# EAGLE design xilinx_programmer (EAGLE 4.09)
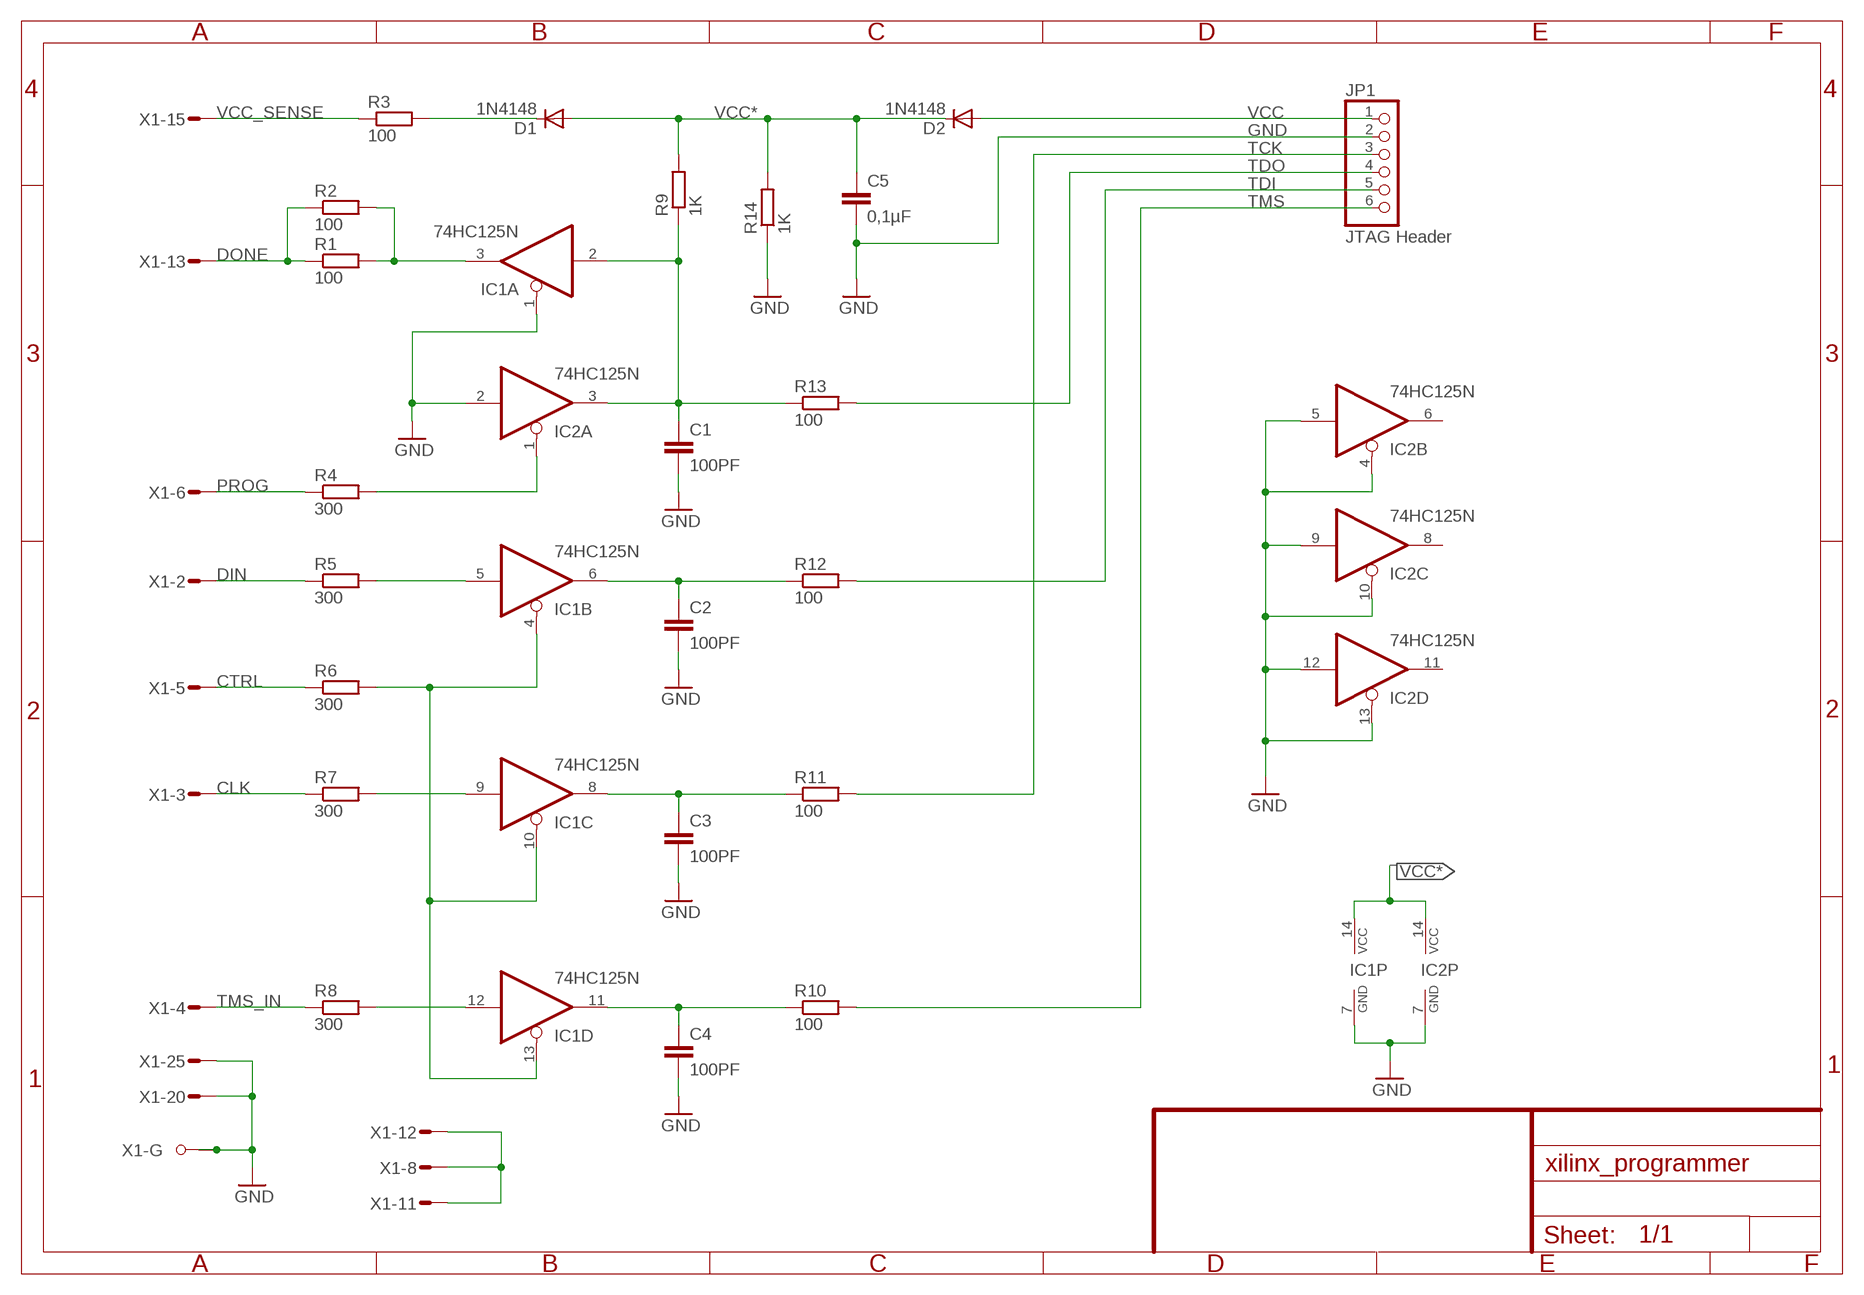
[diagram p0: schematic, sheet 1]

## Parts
C1  100PF  C-EU050-025X075  [C050-025X075]
C2  100PF  C-EU050-025X075  [C050-025X075]
C3  100PF  C-EU050-025X075  [C050-025X075]
C4  100PF  C-EU050-025X075  [C050-025X075]
C5  0,1µF  C-EU050-025X075  [C050-025X075]
D1  1N4148  [DO35-10]
D2  1N4148  [DO35-10]
IC1  74HC125N  [DIL14]
IC2  74HC125N  [DIL14]
JP1  JTAG Header  PINHD-1X6  [1X06]
R1  100  R-EU_0207/10  [0207/10]
R2  100  R-EU_0207/10  [0207/10]
R3  100  R-EU_0207/10  [0207/10]
R4  300  R-EU_0207/10  [0207/10]
R5  300  R-EU_0207/10  [0207/10]
R6  300  R-EU_0207/10  [0207/10]
R7  300  R-EU_0207/10  [0207/10]
R8  300  R-EU_0207/10  [0207/10]
R9  1K  R-EU_0207/10  [0207/10]
R10  100  R-EU_0207/10  [0207/10]
R11  100  R-EU_0207/10  [0207/10]
R12  100  R-EU_0207/10  [0207/10]
R13  100  R-EU_0207/10  [0207/10]
R14  1K  R-EU_0207/10  [0207/10]
X1  M25HPS  [M25HP]

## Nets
CLK: R7.1 X1.3(-3:M)
CTRL: R6.1 X1.5(-5:M)
DIN: R5.1 X1.2(-2:M)
DONE: R1.1 R2.1 X1.13(-13:M)
GND: C1.2 C2.2 C3.2 C4.2 C5.2 IC1.1(A:OE) IC1.7(P:GND) IC2.2(A:I) IC2.4(B:OE) IC2.5(B:I) IC2.7(P:GND) IC2.9(C:I) IC2.10(C:OE) IC2.12(D:I) IC2.13(D:OE) JP1.2 R14.1 X1.20(-20:M) X1.25(-25:M) X1.G1(-G:G1) X1.G2(-G:G2)
N$1: D1.C R3.2
N$3: X1.8(-8:M) X1.11(-11:M) X1.12(-12:M)
N$5: IC1.3(A:O) R1.2 R2.2
N$7: C2.1 IC1.6(B:O) R12.1
N$8: C1.1 IC1.2(A:I) IC2.3(A:O) R9.1 R13.1
N$9: IC2.1(A:OE) R4.2
N$10: IC1.5(B:I) R5.2
N$11: IC1.4(B:OE) IC1.10(C:OE) IC1.13(D:OE) R6.2
N$12: IC1.9(C:I) R7.2
N$13: IC1.12(D:I) R8.2
N$14: C3.1 IC1.8(C:O) R11.1
N$15: C4.1 IC1.11(D:O) R10.1
PROG: R4.1 X1.6(-6:M)
TCK: JP1.3 R11.2
TDI: JP1.5 R12.2
TDO: JP1.4 R13.2
TMS: JP1.6 R10.2
TMS_IN: R8.1 X1.4(-4:M)
VCC: D2.A JP1.1
VCC*: C5.1 D1.A D2.C IC1.14(P:VCC) IC2.14(P:VCC) R9.2 R14.2
VCC_SENSE: R3.1 X1.15(-15:M)
Unconnected: IC2.6(B:O) IC2.8(C:O) IC2.11(D:O) X1.1(-1:M) X1.7(-7:M) X1.9(-9:M) X1.10(-10:M) X1.14(-14:M) X1.16(-16:M) X1.17(-17:M) X1.18(-18:M) X1.19(-19:M) X1.21(-21:M) X1.22(-22:M) X1.23(-23:M) X1.24(-24:M)

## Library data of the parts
C1-C5 = rcl:C-EU: CAPACITOR, European symbol
D1 D2 = diode:1N4148: DIODE
IC1 IC2 = 74xx-eu:74*125: Quad bus BUFFER, 3-state
JP1 = pinhead:PINHD-1X6: PIN HEADER
R1-R14 = rcl:R-EU_: RESISTOR, European symbol
X1 = con-subd:M25HPS: SUB-D

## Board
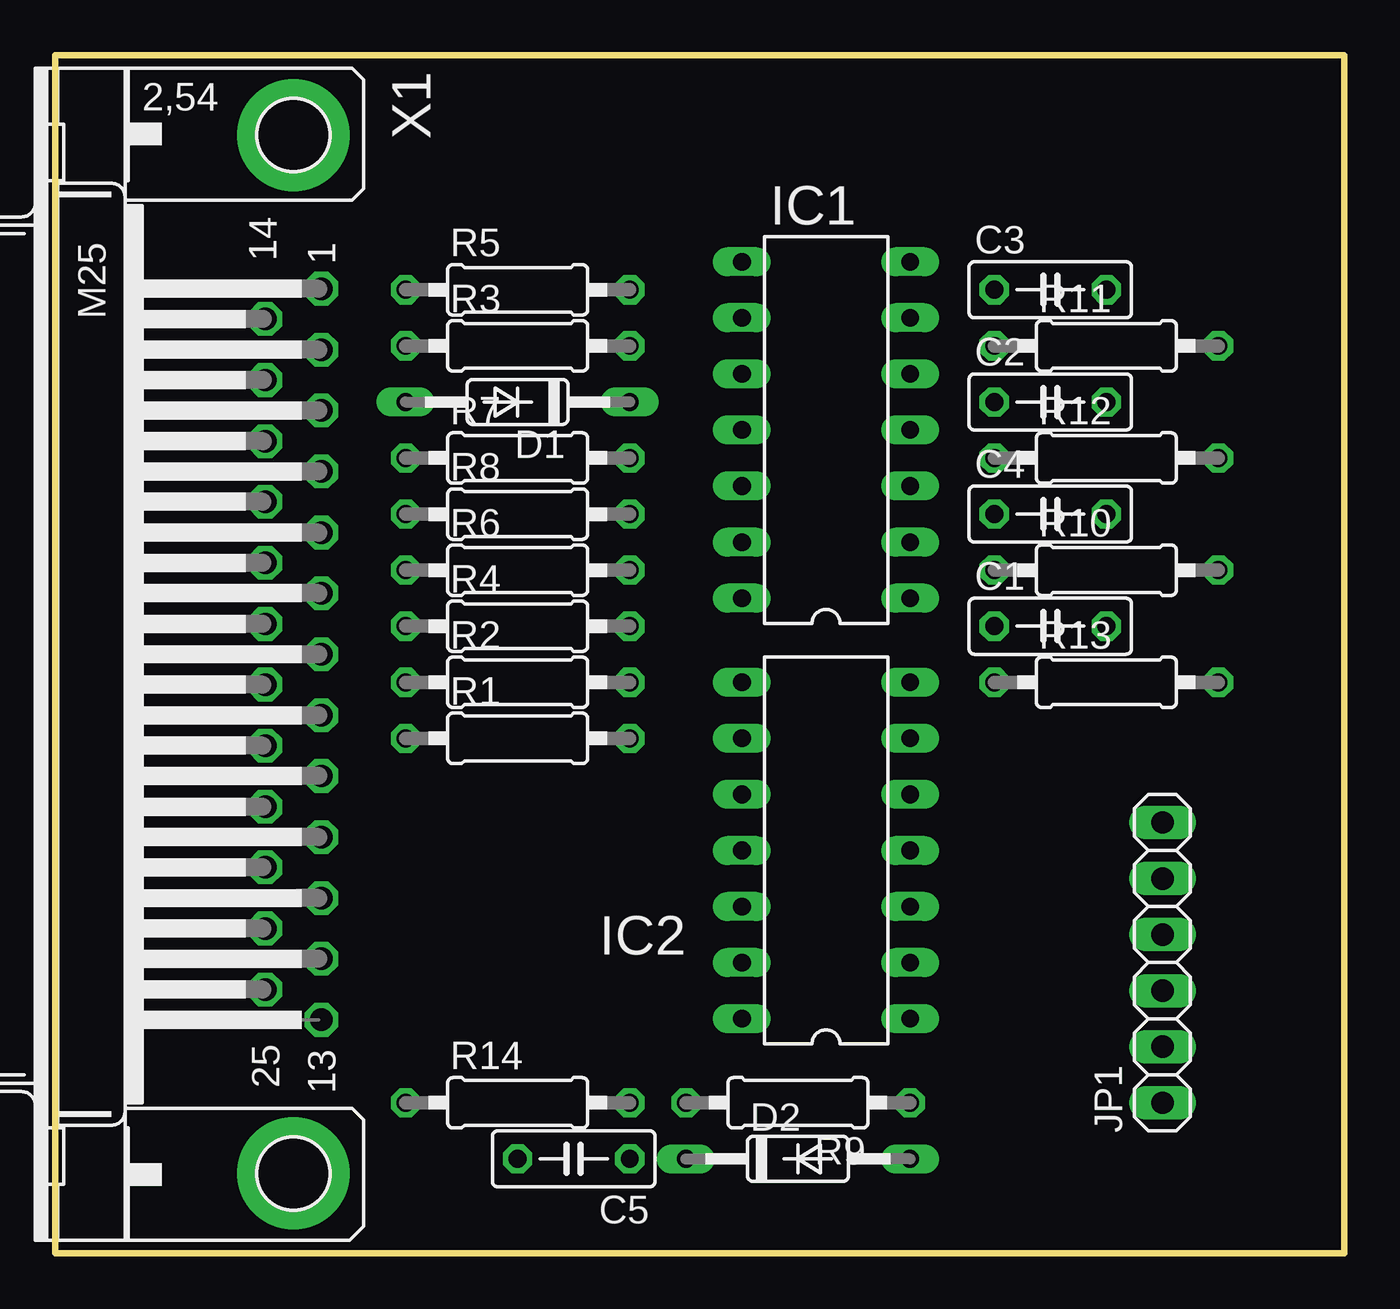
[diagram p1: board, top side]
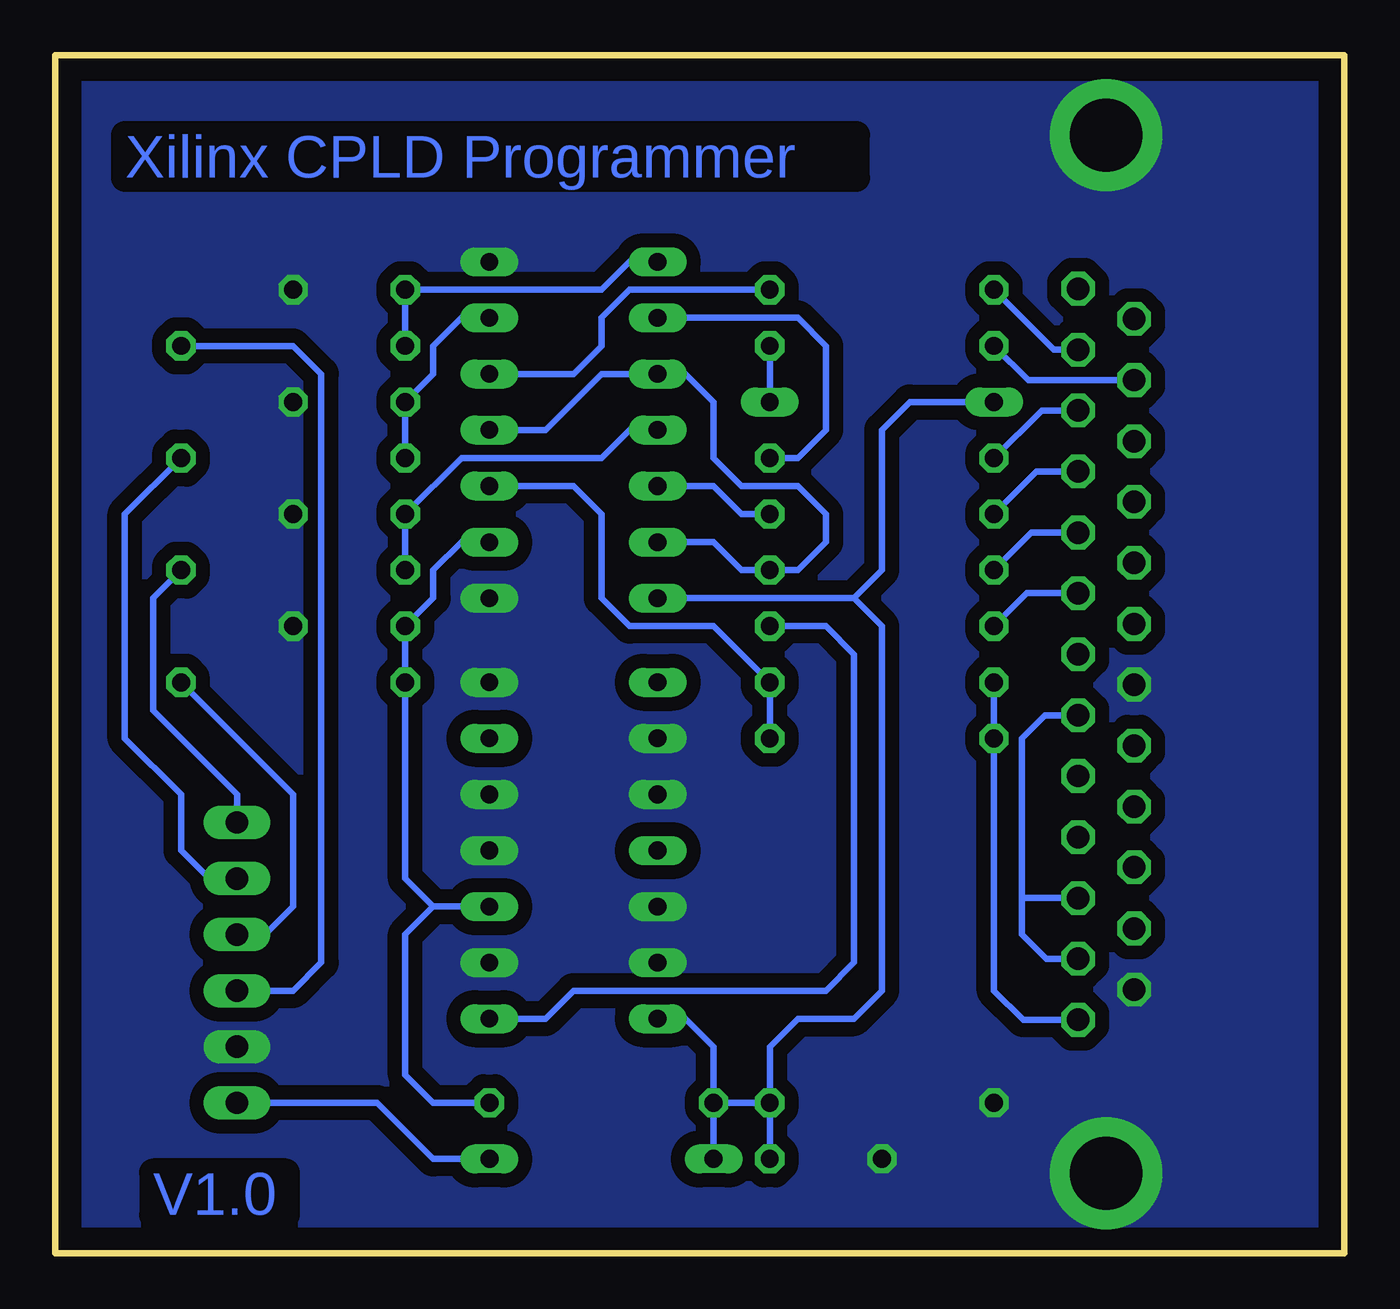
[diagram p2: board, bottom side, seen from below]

Size 58.4 x 54.28 mm. Coordinates in mm from the lower left corner, seen from the top.
Outline: 0,0 58.4,0 58.4,54.28 0,54.28 0,0
Copper layers 16: Bottom 0.035mm
Design rules "default": minimum track width 10mil, minimum drill 24mil, track to track 8mil, track to pad 8mil, pad to pad 8mil, via to via 8mil, smd to smd 8mil, copper to edge 40mil, drill to drill 8mil, minimum pad ring 10mil, minimum via ring 8mil, stop-mask expansion 4mil, vias tented up to drill 0mil, thermal gap 10mil

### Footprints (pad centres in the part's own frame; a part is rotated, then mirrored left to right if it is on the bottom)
C050-025X075 = drill 0.813 octagon: 1 -2.54,0; 2 2.54,0
DO35-10 = drill 0.813 long: A 5.08,0; C -5.08,0
DIL14 = drill 0.8 long: 1 -7.62,-3.81; 2 -5.08,-3.81; 3 -2.54,-3.81; 4 0,-3.81; 5 2.54,-3.81; 6 5.08,-3.81; 7 7.62,-3.81; 8 7.62,3.81; 9 5.08,3.81; 10 2.54,3.81; 11 0,3.81; 12 -2.54,3.81; 13 -5.08,3.81; 14 -7.62,3.81
1X06 = drill 1.016 long: 1 -6.35,0; 2 -3.81,0; 3 -1.27,0; 4 1.27,0; 5 3.81,0; 6 6.35,0
0207/10 = drill 0.813 octagon: 1 -5.08,0; 2 5.08,0
M25HP = drill 1.016 octagon: 1 -16.561,1.27; 2 -13.792,1.27; 3 -11.049,1.27; 4 -8.28,1.27; 5 -5.512,1.27; 6 -2.769,1.27; 7 0,1.27; 8 2.769,1.27; 9 5.512,1.27; 10 8.28,1.27; 11 11.049,1.27; 12 13.792,1.27; 13 16.561,1.27; 14 -15.189,-1.27; 15 -12.421,-1.27; 16 -9.652,-1.27; 17 -6.909,-1.27; 18 -4.14,-1.27; 19 -1.372,-1.27; 20 1.372,-1.27; 21 4.14,-1.27; 22 6.909,-1.27; 23 9.652,-1.27; 24 12.421,-1.27; 25 15.189,-1.27 | drill 3.302 pad 5.08 round: G1 -23.52,0; G2 23.52,0

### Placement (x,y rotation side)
C1  45.08,28.41 0 top
C2  45.08,38.57 0 top
C3  45.08,43.65 0 top
C4  45.08,33.49 0 top
C5  23.49,4.28 180 top
D1  20.95,38.57 180 top
D2  33.65,4.28 0 top
IC1  34.92,37.3 90 top
IC2  34.92,18.25 90 top
JP1  50.16,13.17 90 top
R1  20.95,23.33 0 top
R2  20.95,25.87 0 top
R3  20.95,41.11 0 top
R4  20.95,28.41 0 top
R5  20.95,43.65 0 top
R6  20.95,30.95 0 top
R7  20.95,36.03 0 top
R8  20.95,33.49 0 top
R9  33.65,6.82 180 top
R10  47.62,30.95 0 top
R11  47.62,41.11 0 top
R12  47.62,36.03 0 top
R13  47.62,25.87 0 top
R14  20.95,6.82 0 top
X1  10.79,27.14 270 top

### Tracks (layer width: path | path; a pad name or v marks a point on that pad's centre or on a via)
CLK
  Bottom 0.305: X1.3 13.71,38.19 R7.1
CTRL
  Bottom 0.305: X1.5 14.17,32.65 R6.1
DIN
  Bottom 0.305: X1.2 13.15,40.93 R5.1
DONE
  Bottom 0.305: R2.1 R1.1 15.87,11.9 14.55,10.58 X1.13
GND
  pour Bottom (isolate 0.635, no thermals): 0.63,53.81 57.78,53.81 57.78,0.47 0.63,0.47
N$1
  Bottom 0.305: D1.C R3.2
N$3
  Bottom 0.305: X1.8 13.56,24.37 14.6,23.33 14.6,16.09 | X1.12 13.51,13.35 14.6,14.44 14.6,16.09 | 14.6,16.09 X1.11
N$5
  Bottom 0.305: R1.2 R2.2 28.57,28.41 32.38,28.41 33.65,29.68 33.65,33.49 34.92,34.76 IC1.3
N$7
  Bottom 0.305: R12.1 C2.1 41.27,39.84 41.27,41.11 40,42.38 IC1.6
N$8
  Bottom 0.305: R9.1 41.27,6.82 42.54,8.09 42.54,14.44 41.27,15.71 | 41.27,15.71 IC2.3 | 41.27,15.71 42.54,16.98 R13.1 C1.1 41.27,29.68 41.27,30.95 40,32.22 IC1.2
N$9
  Bottom 0.305: IC2.1 36.19,10.63 34.92,11.9 23.49,11.9 22.22,13.17 22.22,27.14 23.49,28.41 R4.2
N$10
  Bottom 0.305: R5.2 32.38,43.65 33.65,42.38 33.65,41.11 34.92,39.84 IC1.5
N$11
  Bottom 0.305: IC1.13 28.57,32.22 27.3,30.95 R6.2 24.76,30.95 23.49,32.22 23.49,33.49 24.76,34.76 27.3,34.76 28.57,36.03 28.57,38.57 29.84,39.84 IC1.10 33.65,39.84 36.19,37.3 IC1.4
N$12
  Bottom 0.305: R7.2 24.76,36.03 23.49,37.3 23.49,41.11 24.76,42.38 IC1.9
N$13
  Bottom 0.305: R8.2 27.3,33.49 28.57,34.76 IC1.12
N$14
  Bottom 0.305: R11.1 C3.1 33.65,43.65 32.38,44.92 IC1.8
N$15
  Bottom 0.305: R10.1 C4.1 40,36.03 33.65,36.03 32.38,37.3 IC1.11
PROG
  Bottom 0.305: X1.6 14.37,29.91 R4.1
TCK
  Bottom 0.305: JP1.3 47.62,11.9 46.35,13.17 46.35,39.84 47.62,41.11 R11.2
TDI
  Bottom 0.305: R12.2 55.24,33.49 55.24,23.33 52.7,20.79 52.7,18.25 51.43,16.98 JP1.5
TDO
  Bottom 0.305: JP1.4 48.89,14.44 47.62,15.71 47.62,20.79 R13.2
TMS
  Bottom 0.305: R10.2 53.97,29.68 53.97,24.6 50.16,20.79 JP1.6
TMS_IN
  Bottom 0.305: X1.4 13.94,35.42 R8.1
VCC
  Bottom 0.305: D2.A 41.27,4.28 43.81,6.82 JP1.1
VCC*
  Bottom 0.305: D1.A 19.68,38.57 20.95,37.3 20.95,30.95 22.22,29.68 | 22.22,29.68 IC1.14 | 22.22,29.68 20.95,28.41 20.95,11.9 22.22,10.63 24.76,10.63 26.03,9.36 R14.2 | C5.1 R14.2 | R14.2 R9.2 | R9.2 28.57,9.36 29.84,10.63 IC2.14 | R9.2 D2.C
VCC_SENSE
  Bottom 0.305: X1.15 14.32,39.56 R3.1

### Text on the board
Bottom: Xilinx CPLD Programmer | V1.0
